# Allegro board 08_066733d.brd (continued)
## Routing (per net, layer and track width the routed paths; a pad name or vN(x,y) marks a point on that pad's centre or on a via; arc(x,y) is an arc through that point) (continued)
UNNAMED_6_CAP_I1_N1: length 6.6
  TOP w0.14: R20.2 14.5,48.92 12.8,48.92 C166.1 Y1.1
UNNAMED_6_CAP_I3_N1: length 5.5
  TOP w0.14: R22.2 16,52.13 C168.1 ; R27.1 17.65,53.34 17.2,52.89 C168.1 ; C168.1 Y1.3
UNNAMED_6_CAP_I19_N1: length 10.3
  TOP w0.14: U3.7 v1(48.92,20.85) ; R32.2 47.24,27.37 48,27.37 R29.2 48.32,27.19 v1(48.32,26.07) U3.24
  BOTTOM w0.381: v1(48.92,20.85) 48.92,22.4 48.25,23.06 C170.1 48.32,24.14 v1(48.32,26.07)
UNNAMED_6_CAP_I28_N1: length 7.5
  TOP w0.14: v1(51.31,27.18) 50.92,26.79 U3.20
  TOP w0.254: v1(52.96,24.51) 52.77,24.32 U3.16
  TOP w0.305: v1(52.96,24.51) 53.16,24.32 C171.1
  TOP w0.508: R33.2 C171.1
  BOTTOM w0.381: v1(52.96,24.51) 52.64,24.51 51.31,25.84 v1(51.31,27.18)
UNNAMED_6_CAP_I32_N1: length 7.7
  TOP w0.254: U3.11 50.92,21.46 v1(51.11,21.27) ; U3.15 52.77,23.82 v1(52.96,23.62) 53.41,23.18 R39.2
  TOP w0.381: v1(51.11,21.27) 51.11,21.24 51.18,21.17 51.18,21.01 C172.1
  TOP w0.508: R38.2 C172.1
  BOTTOM w0.381: v1(51.11,21.27) 51.11,22.15 52.58,23.62 v1(52.96,23.62)
UNNAMED_6_CAP_I37_N1: length 7.3
  TOP w0.14: R21.2 16.32,43.89 16.18,43.75 12.33,43.75 12.19,43.89 C167.1 Y2.1
UNNAMED_6_CAP_I39_N1: length 4.9
  TOP w0.14: C169.1 R28.1 R23.2 15.81,46.34 15.81,46.34 Y2.3
UNNAMED_6_ICSI5356X_I34_CLK0: length 1.6
  TOP w0.14: U3.22 49.92,26.86 R34.1
UNNAMED_6_ICSI5356X_I34_CLK1: length 1.4
  TOP w0.14: U3.21 R40.1
UNNAMED_6_ICSI5356X_I34_CLK2: length 2.8
  TOP w0.14: U3.18 52.51,25.32 52.71,25.51 52.71,27.19 R35.1
UNNAMED_6_ICSI5356X_I34_CLK4: length 2.3
  TOP w0.14: R36.1 53.09,22.1 52.95,22.24 52.95,23 52.63,23.32 U3.14
UNNAMED_6_ICSI5356X_I34_CLK6: length 1.4
  TOP w0.14: U3.10 R37.1
UNNAMED_6_ICSI5356X_I34_SSCDIS: length 2.7
  TOP w0.14: R31.1 R30.2 46.79,22.79 47.32,23.32 U3.5
UNNAMED_6_ICSI5356X_I34_XA: length 2.5
  TOP w0.14: Y3.3 46.8,26.29 47.77,25.32 U3.1
UNNAMED_6_ICSI5356X_I34_XB: length 6
  TOP w0.14: U3.2 47.72,24.82 47,24.1 47,23.69 46.75,23.43 44,23.43 43.86,23.57 Y3.1
UNNAMED_6_RES_I4_N2: length 2.6
  TOP w0.14: R18.2 18.72,50.74 R20.1 R22.1
UNNAMED_6_RES_I38_N1: length 2.9
  TOP w0.14: R19.2 18.72,46.34 R23.1 R21.1
UNNAMED_6_RES_I72_N1: length 1.6
  BOTTOM w0.14: R141.1 12.06,34.47 Y4.3
UNNAMED_6_RES_I73_N1: length 1.5
  BOTTOM w0.14: Y5.3 R142.1
UNNAMED_6_RES_I74_N1: length 1.7
  BOTTOM w0.14: R144.1 12.11,25.93 Y6.3
UNNAMED_6_RES_I75_N2: length 1.5
  BOTTOM w0.14: Y6.1 15.31,23.63 15.31,23.63 R143.2
UNNAMED_6_RES_I76_N2: length 1.6
  BOTTOM w0.14: Y5.1 R140.2
UNNAMED_6_RES_I77_N2: length 1.7
  BOTTOM w0.14: Y4.1 15.42,33.16 R139.2
UNNAMED_7_CN100PV2_I6_N44: length 9.8
  TOP w0.14: v1(1.27,16.51) 1.73,16.05 1.73,13.51 4.45,10.79 R41.2
  BOTTOM w0.14: v1(1.27,16.51) 1.4,16.64 J3.87
UNNAMED_7_CN100PV2_I6_N45: length 8.5
  TOP w0.14: R42.2 3.17,11.49 1.27,13.4 v1(1.27,15.75)
  BOTTOM w0.14: v1(1.27,15.75) 1.52,16 J3.89
UNNAMED_7_CN100PV2_I6_N46: length 13.5
  TOP w0.14: R43.2 v2(6.98,10.79)
  BOTTOM w0.14: J3.91 1.65,15.37 1.14,14.86 1.14,10.67 1.65,10.16 6.35,10.16 v2(6.98,10.79)
UNNAMED_7_CN100PV2_I6_N47: length 6.2
  TOP w0.14: R44.2 v2(1.91,10.92)
  BOTTOM w0.14: v2(1.91,10.92) 1.52,11.43 1.52,14.22 2.03,14.73 J3.93
UNNAMED_7_CN100PV2_I6_N48: length 8.2
  TOP w0.14: v2(5.59,10.79) 5.59,10.15 R45.2
  BOTTOM w0.14: J3.95 2.16,14.1 1.91,13.84 1.91,12.06 3.17,10.79 v2(5.59,10.79)
UNNAMED_8_ICIS25LP512_I14_SCK: length 3
  TOP w0.14: R50.1 R49.2 9.15,28.46 9.55,28.85 U4.16
UNNAMED_8_ICIS25LP512_I14_SO: length 3.1
  TOP w0.14: U4.8 v2(17.78,38.23)
  BOTTOM w0.14: R51.2 17.03,38.23 v2(17.78,38.23) R52.1
UNNAMED_9_ADSPSC59X_I10_HADC0VREFN: length 3.3
  TOP w0.305: U1.N20 41.53,51.34
  TOP w0.381: 41.53,51.34 41.93,51.74 R58.1
UNNAMED_9_ADSPSC59X_I10_HADC0VREFP: length 24.2
  TOP w0.203: U1.R19 v1(40.22,49.34)
  TOP w0.508: FL2.3 50.94,57.23 50.43,57.74 v1(49.52,57.74) C178.1 C177.1
  L8_SIG w0.292: v1(40.22,49.34) 41.06,49.46
  L8_SIG w0.381: 41.06,49.46 46.74,49.46
  L8_SIG w0.508: 46.74,49.46 47.5,50.22 47.5,51.84 48.3,52.64 49.32,52.64 50.32,53.64 50.32,56.94 v1(49.52,57.74)
UNNAMED_9_DIOLED_I5_N: length 2.9
  TOP w0.14: DS6.C 22.43,68.97 22.29,68.83 21.46,68.83 21.32,68.69 R59.1
UNNAMED_10_7408V3_I4_Y: length 15.5
  TOP w0.14: U13.1 58.32,30.79 58.87,30.24 59.42,30.24 59.56,30.1 60.96,30.1 v1(61.72,30.86) ; v1(61.72,38.23) 60.96,37.78 59.57,37.78 U11.4
  L4_SIG w0.127: v1(61.72,30.86) 60.71,31.88 60.71,37.21 v1(61.72,38.23)
UNNAMED_10_7408V3_I7_B: length 14.1
  TOP w0.14: S2.2B 60.18,36 56.66,36 S2.2A 56.09,35.43 55.25,35.43 54.8,34.99 54.8,33.46 54.23,32.89 54.23,30.73 55.11,29.85 R70.2 57.26,29.85 U13.2
UNNAMED_10_7408V3_I7_Y: length 8.8
  TOP w0.14: U13.4 60.31,28.9 60.71,28.5 60.71,24.26 60.25,23.8 U14.3 59.31,23.69 R71.2
UNNAMED_10_DIOLED_I24_N: length 2.1
  TOP w0.14: R73.1 DS5.C
UNNAMED_10_DIOLED_I40_N: length 2.1
  TOP w0.14: R77.1 DS4.C
UNNAMED_10_DIOLED_I62_N: length 2.1
  TOP w0.14: R76.1 DS1.C
UNNAMED_10_DIOLED_I63_N: length 2.1
  TOP w0.14: R74.1 DS2.C
UNNAMED_10_DIOLED_I64_N: length 2.1
  TOP w0.14: R72.1 DS3.C
UNNAMED_10_ICMC23018_I57_ADDR: length 2.7
  TOP w0.14: U24.11 14.11,65.46 R65.1 R64.2
UNNAMED_10_ICMC23018_I57_GPA0: length 9.1
  TOP w0.14: U24.15 12.07,62.86 v2(11.75,63.18)
  TOP w0.305: v2(5.46,64.81) R76.2
  L5_SIG w0.127: v2(11.75,63.18) 7.09,63.18 v2(5.46,64.81)
UNNAMED_10_ICMC23018_I57_GPA1: length 11.7
  TOP w0.14: U24.16 11.49,62.36 11.24,62.61 10.41,62.61 v2(9.78,61.98)
  TOP w0.305: R74.2 v2(3.56,64.81)
  L5_SIG w0.127: v2(3.56,64.81) 6.39,61.98 v2(9.78,61.98)
UNNAMED_10_ICMC23018_I57_GPA2: length 13.8
  TOP w0.14: v2(10.79,61.98) 10.91,61.86 U24.17
  TOP w0.305: v2(1.65,64.81) R72.2
  L5_SIG w0.127: v2(1.65,64.81) 5.06,61.4 10.22,61.4 v2(10.79,61.98)
UNNAMED_12_CAP_I12_N1: length 8.9
  TOP w0.254: v2(12.19,87.12) 12.2,87.11 U15.19
  BOTTOM w0.305: C185.1 v2(12.19,87.12) C186.1
  BOTTOM w0.508: E1.2 17.4,89.7 16.22,88.52 13.97,88.52 12.96,87.51 C186.1
UNNAMED_12_CAP_I23_N1: length 22.3
  TOP w0.254: U15.16 13.91,89.03 v2(13.08,89.03) ; v2(19.81,84.33) 19.43,84.61 U15.1
  TOP w0.762: v2(19.81,84.33) 20.57,84.33 20.83,84.58 20.83,90.3 20.45,90.68 13.46,90.68 13.08,90.3 v2(13.08,89.03)
  BOTTOM w0.305: R88.1 13.08,89.03 v2(13.08,89.03) ; v2(19.81,84.33) C187.1 C188.1
UNNAMED_12_CMOSPI3C3125_I39_B0: length 21.7
  TOP w0.14: U15.8 19.78,88.11 v2(19.81,88.14) ; v2(11.05,77.47) 11.43,77.74 U7.3
  L4_SIG w0.127: v2(19.81,88.14) 18.67,86.99 14.16,86.99 12.63,85.46 11.88,85.46 11.61,85.19 11.61,78.03 v2(11.05,77.47)
  BOTTOM w0.14: R86.2 11.44,77.86 v2(11.05,77.47)
UNNAMED_12_CMOSPI3C3125_I39_B1: length 16
  TOP w0.14: v2(17.4,82.68) 17.63,83.18 U15.32 ; U7.6 11.43,75.79 v2(11.05,76.07)
  L4_SIG w0.127: v2(17.4,82.68) 16.64,83.44 14.48,83.44 13.02,81.98 13.02,78.04 v2(11.05,76.07)
  BOTTOM w0.14: v2(11.05,76.07) 11.3,76.32 R87.2
UNNAMED_12_CMOSPI3C3125_I39_B2: length 14.9
  TOP w0.14: U7.8 19.3,75.14 v2(20.19,74.8) ; U15.2 19.43,85.11 v2(19.81,85.47)
  L8_SIG w0.127: v2(19.81,85.47) 19.18,84.84 19.18,75.82 v2(20.19,74.8)
UNNAMED_12_CMOSPI3C3125_I39_B3: length 9.1
  TOP w0.14: v2(16.38,82.68) 16.63,83.18 U15.30 ; U7.11 16.89,77.09 v2(16.89,77.09)
  L4_SIG w0.127: v2(16.89,77.09) 17.65,77.85 17.65,81.41 v2(16.38,82.68)
UNNAMED_12_CN10PODDEVEN_I8_N5: length 4.4
  TOP w0.14: P6.10 8.01,49.91 R85.1
UNNAMED_12_DIOLED_I30_N: length 1.9
  TOP w0.14: R89.1 DS7.C
UNNAMED_12_DIOLED_I31_N: length 1.9
  TOP w0.14: R90.1 DS8.C
UNNAMED_12_ICFT232RQ_I37_CBUS0: length 13.4
  TOP w0.14: v2(11.18,86.11) 11.81,85.47 12.66,85.47 12.8,85.61 U15.22 ; R89.2 v2(4.45,93.34)
  L4_SIG w0.127: v2(11.18,86.11) 4.45,92.84 v2(4.45,93.34)
UNNAMED_12_ICFT232RQ_I37_CBUS1: length 11.7
  TOP w0.14: U15.21 12.2,86.11 v2(12.19,86.11) ; R90.2 v2(6.35,93.34)
  L4_SIG w0.127: v2(12.19,86.11) 6.35,91.95 v2(6.35,93.34)
UNNAMED_12_ICFT232RQ_I37_RESET: length 3.5
  TOP w0.14: U15.18 12.54,87.61 12.44,87.71 12.11,87.71 11.68,88.14 v2(11.18,88.14)
  BOTTOM w0.14: R88.2 10.87,88.45 v2(11.18,88.14)
UNNAMED_13_ADLT8636_I1_BST: length 1.9
  TOP w0.254: C207.1 18.78,19 VR1.7
UNNAMED_13_ADLT8636_I1_EN: length 2.6
  TOP w0.203: v1(15.94,14.99) 16.14,14.99 VR1.14
  BOTTOM w0.305: R95.2 R96.2 15.62,15.29 15.93,14.99 v1(15.94,14.99)
UNNAMED_13_ADLT8636_I1_FB1: length 5.2
  TOP w0.254: 18.28,12.7 18.28,11.35 C210.2 ; 18.28,12.7 VR1.19 ; 18.28,12.7 18.54,12.7 18.53,12.7 18.78,12.95 VR1.20
  TOP w0.305: R106.1 R105.2 C210.2
UNNAMED_13_ADLT8636_I1_RT: length 2.5
  TOP w0.254: R98.1 16.13,11.94 17.28,13.09 VR1.17
UNNAMED_13_ADLT8636_I1_SYNC: length 2.6
  TOP w0.254: VR1.15 16.2,14.49 15.55,13.84
  TOP w0.305: 15.55,13.84 R94.1 R93.1
UNNAMED_13_ADLT8636_I1_TR: length 2.3
  TOP w0.254: C204.1 17.21,12.07 17.78,12.64 VR1.18
UNNAMED_13_ADLTC3307_I3_FB: length 3.6
  TOP w0.254: C220.2 R109.1 ; C220.2 U17.12 ; C220.2 R108.2
UNNAMED_13_ADLTC3307_I3_MODE: length 1.8
  TOP w0.14: U17.9 43.63,14.67 v1(43.56,14.61)
  BOTTOM w0.508: R5.2 42.97,14.61 v1(43.56,14.61)
UNNAMED_13_ADLTC3310_I4_FB: length 10.5
  TOP w0.254: U16.18 C208.2
  TOP w0.305: 33.66,13.58 C208.2 ; 33.66,13.58 34.54,13.58 R101.2 35.81,13.71 R102.1 ; 33.66,13.58 33.66,11.66 34.14,11.17 R97.2 R107.1 C209.1
UNNAMED_13_ADLTC3310_I4_ITH: length 9.5
  TOP w0.254: 31.68,13.58 32.38,14.28 U16.17
  TOP w0.305: C193.1 C195.1 31.68,13.58 31.94,13.32 31.94,10.73 32.5,10.17 R97.1
UNNAMED_13_ADLTC3310_I4_PGOOD: length 2.2
  TOP w0.254: U16.14 30.73,15.64 30.1,15.64 29.46,14.99 R99.1
UNNAMED_13_ADLTC3310_I4_SSTT: length 3.9
  TOP w0.254: U16.16 31.88,14.73 31.44,14.29 29.72,14.29 29.08,13.65 C202.1
UNNAMED_13_CAP_I72_N2: length 2.8
  TOP w0.305: C195.2 31.11,10.86 30.87,10.61 R91.1
UNNAMED_13_RES_I58_N2: length 1.7
  TOP w0.305: R102.2 36.07,12.71 37.27,12.71 R103.1
UNNAMED_14_CAP_I4_N1: length 2.7
  L2_PWR w0.14: v1(44.26,32.07) 45.21,33.02 v3(45.21,33.38)
  BOTTOM w0.14: v1(44.26,32.07) 44.32,32 C232.1
UNNAMED_14_CMOSSN74CB3T3125_I44_2B: length 4.1
  TOP w0.14: v1(22.16,35.18) 22.81,35.83 U12.6
  BOTTOM w0.14: v1(22.16,35.18) 22.81,35.83 R119.2 23.13,35.83 23.51,35.44 23.51,35.41 24.09,34.83 R68.1
UNNAMED_14_ICIS2XES04G_I1_CLK: length 1.9
  TOP w0.14: U19.M6 49.35,35.74 v1(49.21,35.74)
  BOTTOM w0.14: v1(49.21,35.74) 49.83,35.74 49.97,35.88 R110.2
UNNAMED_16_CAP_I2_N1: length 22.8
  TOP w0.305: P1.B9 31.73,92.22 P1.A4 ; P1.B4 29.23,92.22 P1.A9 29.23,89.77 C158.1
  TOP w0.508: C158.1 D15.C
  BOTTOM w0.508: v2(36.83,98.55) v2(36.83,97.79) 36.83,92.07 36,91.25 31.68,91.25 ; 31.68,91.25 29.46,91.25 29.28,91.43 P1.B4 ; 31.68,91.25 P1.B9
  vias: v2(42.16,99.63) v2(42.16,98.87) v2(42.16,98.11) v2(42.16,97.35)
UNNAMED_16_CAP_I15_N1: length 7.5
  TOP w0.508: R124.1 36.83,92.84 C159.1 36.83,92.97
  TOP w0.889: D16.C 39.37,95.16 39.15,95.38 R123.2 36.83,92.97
UNNAMED_16_CAP_I20_N1: length 2.7
  TOP w0.254: U6.21 v2(46.6,96.25)
  BOTTOM w0.508: v2(46.6,96.25) 48.18,96.25 C199.1
UNNAMED_16_CAP_I21_N1: length 1.9
  TOP w0.254: U6.23 v2(45.6,96.25)
  BOTTOM w0.508: C200.1 45.55,96.3 v2(45.6,96.25)
UNNAMED_16_CAP_I27_N2: length 1.3
  TOP w0.305: C160.2 R130.2
UNNAMED_16_CAP_I38_N1: length 47.6
  TOP w0.203: 30.48,99.45 P1.SH6 30.48,97.95 ; 30.48,94.86 P1.SH5 30.48,96.35
  TOP w0.508: P1.SH4 35.6,96.99 ; P1.SH4 33.9,99.31 ; P1.SH4 35.6,99.31 ; P1.SH4 33.9,96.99 ; 25.36,94.58 P1.SH2 ; P1.SH2 25.36,92.26 ; P1.SH2 27.06,94.58 ; P1.SH1 35.6,92.26 ; P1.SH1 35.6,94.58 ; P1.SH1 33.9,94.58 ; 25.36,96.99 P1.SH3 ; P1.SH3 25.36,99.31 ; P1.SH3 27.06,99.31 ; P1.SH3 27.06,96.99
  BOTTOM w0.508: P1.SH1 35.6,94.58 ; P1.SH1 33.9,94.58 ; P1.SH1 35.6,92.26 ; P1.SH4 35.6,99.31 ; P1.SH4 33.9,96.99 ; P1.SH4 35.6,96.99 ; P1.SH4 33.9,99.31 ; 25.36,92.26 P1.SH2 ; P1.SH2 25.36,94.58 ; P1.SH2 27.06,94.58 ; R80.1 C184.1 24.31,98.69 24.85,98.15 P1.SH3 ; P1.SH3 27.06,99.31 ; P1.SH3 27.06,96.99 ; P1.SH3 25.36,96.99 ; P1.SH3 25.36,99.31
UNNAMED_16_CN24PAB2GND6SHLD_I6_N5: length 25.9
  TOP w0.254: U6.2 43.94,94.22 v2(43.56,94.49) 43.94,94.72 U6.1
  TOP w0.305: P1.A5 31.23,90.31 31.25,90.29 31.25,90.29 31.44,90.1 31.44,90.1 31.62,89.92 31.62,88.24 31.32,87.93 D17.3 v2(30.59,87.21) ; v2(43.56,94.49) 43.56,94.49 R6.1
  L8_SIG w0.305: v2(30.59,87.21) 31.2,87.82 32.26,87.82 35.75,91.31 40.64,91.31 41.02,90.93 42.74,90.93 44.32,92.52 44.32,93.73 v2(43.56,94.49)
UNNAMED_16_CN24PAB2GND6SHLD_I7_N5: length 29.6
  TOP w0.254: U6.5 43.94,92.72 v2(43.56,92.96) 43.94,93.22 U6.4
  TOP w0.305: v2(43.56,92.96) 43.56,92.96 R66.1 ; D17.1 v2(29.59,89.23)
  L8_SIG w0.305: v2(29.59,89.23) 30.21,89.23 31.05,88.39 31.88,88.39 35.43,91.95 41.1,91.95 41.47,91.58 42.18,91.58 v2(43.56,92.96)
  BOTTOM w0.305: P1.B5 29.68,93.48 29.38,93.79 27.76,93.79 27.39,93.42 27.39,92.99 26.92,92.52 26.92,90.23 27.93,89.23 v2(29.59,89.23)
UNNAMED_16_ICSTUSB4500_I31_ADDR0: length 1.3
  TOP w0.254: U6.12 R125.1
UNNAMED_16_ICSTUSB4500_I31_ADDR1: length 2.8
  TOP w0.254: R126.1 49.09,90.54 49.09,92.01 48.87,92.22 U6.13
UNNAMED_16_ICSTUSB4500_I31_DISCH: length 12.2
  TOP w0.254: U6.9 46.11,90.93 v2(46.61,90.42)
  TOP w0.305: R146.2 v2(53.98,93.98)
  L8_SIG w0.305: v2(53.98,93.98) 53.98,92.58 53.09,91.69 46.91,91.69 46.61,91.39 v2(46.61,90.42)
UNNAMED_16_ICSTUSB4500_I31_VBUSENSNK: length 11.1
  TOP w0.254: v2(49.47,93.72) U6.16
  TOP w0.305: R129.2 v2(55.25,97.54)
  L8_SIG w0.305: v2(55.25,97.54) 51.69,97.54 51.05,96.9 51.05,94.03 50.75,93.72 v2(49.47,93.72)
UNNAMED_16_ICSTUSB4500_I31_VBUSVSDISCH: length 15.4
  TOP w0.254: v2(49.53,94.74) 49.51,94.72 U6.18
  TOP w0.305: R124.2 40.89,92.84 v2(40.89,92.84)
  L8_SIG w0.305: v2(40.89,92.84) 40.89,96.27 41.28,96.65 44.51,96.65 45.02,97.16 47.12,97.16 v2(49.53,94.74)
UNNAMED_16_RES_I22_N2: length 16
  TOP w0.305: R130.1 56.52,99.03 56.11,99.43 R129.1 53.62,99.43 Q5.4 53.4,99.4 53.4,100.27 53.09,100.58 47.88,100.58 47.62,100.33 R128.2 47.62,99.54 47.49,99.4 Q4.4
USB_DM: length 42.1
  TOP w0.133: v1(15.11,94.74) 14.86,94.49 14.86,94.22 14.97,94.11 D2.1 ; U15.15 14.63,89.28 14.73,89.39 14.73,89.53 v1(14.48,89.79) ; P1.A7 30.24,91.02 30.33,90.93 30.33,90.11 v1(30.06,89.84)
  L4_SIG w0.089: v1(15.11,94.74) 15.11,94.31 14.88,94.07 14.88,93.72 15.05,93.56 15.95,93.56 15.95,93.56 16.11,93.56 18.46,95.9 29.87,95.9 30.58,95.19 30.58,92.8 30.88,92.5 P1.B7 30.88,91.85 30.61,91.58 30.61,91.26 30.74,91.12 31.91,91.12 32.19,90.84 32.19,89.34 31.8,88.94 30.6,88.94 30.36,89.18 30.36,89.54 v1(30.06,89.84)
  BOTTOM w0.133: v1(15.11,94.74) 14.86,95 14.86,95.73 14.58,96.01 13.72,96.01 13.14,95.44 13.14,91.78 13.71,91.22 14.4,91.22 14.73,90.89 14.73,90.04 v1(14.48,89.79)
USB_DP: length 40.4
  TOP w0.133: P1.A6 30.63,90.92 30.63,90.13 v1(30.92,89.84) ; v1(14.35,94.74) 14.61,94.49 14.61,94.24 14.47,94.11 D2.2 ; v1(15.24,89.79) 14.99,89.53 14.99,89.42 15.12,89.28 U15.14
  L4_SIG w0.089: v1(14.35,94.74) 14.35,94.31 14.57,94.09 14.57,93.59 14.92,93.25 16.18,93.25 18.57,95.64 29.76,95.64 30.32,95.08 30.32,92.79 30.08,92.55 P1.B6 30.08,91.84 30.3,91.62 30.3,91.13 30.57,90.86 31.8,90.86 31.93,90.73 31.93,89.45 31.68,89.21 30.77,89.21 30.67,89.31 30.67,89.6 v1(30.92,89.84)
  BOTTOM w0.133: v1(14.35,94.74) 14.61,95 14.61,95.62 14.47,95.76 13.82,95.76 13.4,95.34 13.4,91.89 13.81,91.47 14.51,91.47 14.99,91 14.99,90.04 v1(15.24,89.79)
USB_TYPEC: length 9.6
  TOP w0.254: v2(43.37,95.5) 45.07,95.5 U6.24
  TOP w0.305: v2(52.07,96.01) D18.C ; v2(55.25,96.52) C160.1 ; v2(53.98,96.52) R146.1
  TOP w0.508: v2(17.78,93.66) D1.1
  BOTTOM w0.305: v2(42.04,96.01) C201.1
  BOTTOM w0.508: v1(22.29,89.73) E1.1 C183.1
  vias: v2(4.57,17.14) v2(4.57,16.38) v2(4.57,15.62) v2(5.46,17.14) v2(5.46,16.38) v2(5.46,15.62) v2(48.77,99.57) v2(48.77,98.81) v2(48.77,98.04) v2(48.77,97.28) v2(49.53,99.57) v2(49.53,98.81) v2(49.53,98.04) v2(49.53,97.28)
VTT: length 25
  TOP w0.254: U2.6 56.37,73.39
  TOP w0.267: U2.9 54.87,73.92 54.99,74.04
  BOTTOM w0.203: RN7.8 34.06,85.69 34.06,86.22 ; 33.56,86.54 RN7.7
  BOTTOM w0.254: 36.27,86.34 36.27,85.69 RN4.5 ; 44.02,76.69 43.28,76.69 RN1.7 ; 44.02,76.69 44.02,77.19 ; 44.02,76.69 44.02,76.19 43.42,76.19 RN1.8 ; 44.02,72.99 43.37,72.99 RN2.8 ; RN6.5 34.57,67.39 34.57,66.74 ; 44.02,80.39 RN3.6 ; 44.02,79.39 43.37,79.39 RN3.8 ; 44.02,77.19 44.02,77.69 43.42,77.69 RN1.5 ; 44.02,77.19 43.28,77.19 RN1.6 ; RN5.5 37.77,67.39 37.77,66.74 ; RN4.6 36.77,86.34 ; 44.02,73.49 RN2.7 ; RN4.7 37.27,86.34 ; 37.27,66.74 RN5.6 ; RN5.7 36.77,66.74 ; RN3.5 43.37,80.89 44.02,80.89 ; 33.07,66.74 33.07,67.39 RN6.8 ; 34.07,66.74 RN6.6 ; 33.57,66.74 RN6.7 ; 37.77,86.34 37.77,85.69 RN4.8 ; RN5.8 36.27,67.39 36.27,66.74 ; 44.02,74.49 43.37,74.49 RN2.5 ; 44.02,73.99 RN2.6 ; 44.02,79.89 RN3.7
  vias: v2(56.77,77.72) v2(56.77,76.96) v2(56.77,76.2) v2(56.77,75.44) v2(56.77,74.68) v2(56.77,73.91) v2(57.53,77.72) v2(57.53,76.96) v2(57.53,76.2) v2(57.53,75.44) v2(57.53,74.68) v2(57.53,73.91) v2(57.73,72.95) v2(57.73,72.18) v2(58.29,77.72) v2(58.29,76.96) v2(58.29,76.2) v2(58.29,75.44) v2(58.29,74.68) v2(58.29,73.91) v2(59.05,77.72) v2(59.05,76.96) v2(59.05,76.2) v2(59.05,75.44) v2(59.05,74.68) v2(59.05,73.91)

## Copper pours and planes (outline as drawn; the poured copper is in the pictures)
DGND on TOP (solid shape): 62.04,71.88 59.84,71.88 59.84,78.1 62.04,78.1
DGND on TOP (solid shape): 62.04,66.93 59.84,66.93 59.84,71.5 62.04,71.5
DGND on TOP: 10.34,23.34 13.03,23.34 13.03,25.39 12.83,25.59 10.48,25.59 10.34,25.45
DGND on TOP: 45.77,15.53 46.74,15.53 46.91,15.7 48.51,15.7 48.73,15.93 50.66,15.93 51.05,16.32 51.05,20.07 48.26,20.07 48.26,17.08 47.62,16.45 46.41,16.45 45.77,15.81
DGND on TOP: 30.43,12.87 27.6,12.87 27.3,12.57 27.3,8.83 27.62,8.51 38.35,8.51 38.8,8.95 38.8,14.41 36.94,16.28 33.32,16.28 33.32,16 34.17,16 35.62,14.54 36.45,14.54 36.83,14.16 36.83,13.83 38.23,13.83 38.35,13.7 38.35,9.59 37.85,9.08 29.72,9.08 29.15,9.65 29.15,11.05 29.39,11.3 30.47,11.3 30.47,12.83
DGND on TOP: 18.16,15.63 16.25,15.63 15.51,16.37 15.51,16.55 10.16,16.55 10.15,16.54 10.15,13.67 10.41,13.4 13.21,13.4 13.4,13.59 13.4,14.61 13.74,14.95 15.51,14.95 15.91,15.35 18.16,15.35
DGND on TOP: 62.8,100.9 62.8,0.7 0.7,0.7 0.7,100.9 ; 53 cut-outs
DGND on TOP: 45.77,14.31 45.77,13.22 45.85,13.14 46.93,13.14 47.12,12.95 47.12,12.07 46.93,11.88 46.05,11.88 46.05,11.04 46.36,10.73 47.94,10.73 49.19,11.98 49.19,13.48 49.02,13.65 46.42,13.65 46.21,13.86 46.21,14.31
DGND on TOP: 44.4,15.53 43.43,15.53 43.26,15.7 41.66,15.7 41.44,15.93 39.51,15.93 39.12,16.32 39.12,20.07 41.78,20.07 41.78,17.21 42.55,16.45 43.76,16.45 44.4,15.81
DGND on TOP: 14.66,13.15 13.6,13.15 13.46,13.02 13.46,9.21 14.03,8.64 23.94,8.64 24.24,8.94 24.24,11.09 22.24,11.09 21.76,10.61 20.02,10.61 20.02,9.41 19.81,9.21 17.84,9.21 17.54,9.51 17.54,10.59 17.51,10.61 15.76,10.61 14.66,11.72
DGND on BOTTOM: 37.63,23.19 37.63,16.28 39.24,14.67 46.61,14.67 47.18,15.24 47.18,17.11 47.17,17.12 42.13,17.12 41.91,17.34 41.91,22.63 41.35,23.19
DGND on BOTTOM: 0.7,100.9 62.8,100.9 62.8,0.7 0.7,0.7 ; 52 cut-outs
DGND on L2_PWR: 50.8,100.9 62.8,100.9 62.8,65.15 57.15,65.15 57.15,74.04 57.08,74.22 56.9,74.3 50.8,74.3
DGND on L2_PWR: 40.13,39.18 44.83,39.18 44.83,34.8 44.91,34.62 45.09,34.54 49.15,34.54 49.15,33.78 49.22,33.6 49.4,33.53 50.48,33.53 50.48,30.92 40.13,30.92 ; 1 cut-out
DGND on L3_GND: 0.7,100.9 62.8,100.9 62.8,0.7 0.7,0.7
DGND on L3_GND: 28.28,9.89 28.29,9.88 28.31,9.87 35.61,9.87 35.63,9.87 35.94,9.99 36.26,9.87 36.27,9.87 38.05,9.87 38.07,9.88 38.07,9.89 38.07,16.46 38.07,16.48 38.05,16.48 37.67,16.48 37.66,16.48 37.65,16.47 37.21,16.17 36.77,16.47 36.76,16.48 36.75,16.48 36.28,16.48 36.26,16.48 36.25,16.47 35.81,16.17 35.38,16.47 35.37,16.48 35.35,16.48 35.26,16.48 35.25,16.48 35.24,16.47 34.8,16.17 34.36,16.46 34.34,16.47 34.32,16.45 34.32,14.92 34.34,14.9 34.36,14.91 35.27,14.73 34.36,14.55 34.34,14.57 34.32,14.54 34.32,13.65 34.31,13.63 34.29,13.63 28.31,13.63 28.29,13.62 28.28,13.6
DGND on L6_PWR: 30.42,88.01 62.8,88.01 62.8,72.33 51.82,72.33 51.64,72.25 51.56,72.07 51.56,65.28 35.12,65.28 35.12,66.99 38.29,66.99 38.47,67.07 38.54,67.25 38.54,68.26 40.45,68.26 40.63,68.34 40.7,68.52 40.7,70.74 41.53,70.74 41.71,70.81 41.78,70.99 41.78,72.39 42.61,72.39 42.79,72.46 42.86,72.64 42.86,74.68 42.79,74.86 42.61,74.93 41.85,74.93 41.85,75.63 42.61,75.63 42.79,75.7 42.86,75.88 42.86,77.91 42.79,78.09 42.61,78.17 41.85,78.17 41.85,78.8 42.61,78.8 42.79,78.88 42.86,79.06 42.86,81.92 42.79,82.09 42.61,82.17 39.94,82.17 39.94,86.04 39.87,86.22 39.69,86.3 30.42,86.3
DGND on L9_GND: 62.8,100.9 62.8,0.7 0.7,0.7 0.7,100.9
VDD_CONNECTOR on TOP (solid shape): 3.71,14.45 4.45,13.72 5.71,13.72 5.71,12.57 3.3,12.57 2.44,13.44 2.44,18.41 3.71,18.41
VDD_DMC on TOP: 59.44,71.5 57.24,71.5 57.24,70.39 56.85,69.99 55.37,69.99 55.37,66.67 59.44,66.67
VDD_DMC on TOP: 40.07,23.81 40.07,21.08 40.7,20.45 42.16,20.45 43.37,19.24 46.94,19.24 46.94,21.07 46.8,21.21 44.39,21.21 43.82,21.78 43.82,22.1 41.91,24 40.26,24
VDD_DMC on BOTTOM: 47.17,17.93 42.37,17.93 42.37,20.57 42.24,20.7 40.7,20.7 40.01,21.4 40.01,23.11 40.83,23.94 42.48,23.94 44.2,22.22 45.72,22.22 45.91,22.03 45.91,21.27 47.17,20.02
VDD_DMC on L6_PWR: outline of 101 points within 0.7,0.7 62.8,88.01
VDD_EXT on TOP (solid shape): 10.67,5.71 7.75,5.71 7.75,7.62 10.67,7.62
VDD_EXT on TOP (solid shape): 59.18,61.21 57.15,61.21 56.36,60.42 56.36,59.44 52.06,59.44 52.06,62.66 53.47,64.07 59.18,64.07
VDD_EXT on L5_SIG (solid shape): 10.67,5.71 7.75,5.71 7.75,7.62 10.67,7.62
VDD_EXT on TOP: 21.68,20.12 21.68,26.96 20.95,27.69 15.24,27.69 14.4,26.85 14.4,23.99 18.8,23.99 20.1,22.68 20.1,20.12
VDD_EXT on TOP: 33.32,16.5 34.24,16.5 34.42,16.32 37.66,16.32 37.83,16.5 37.83,18.58 35.83,18.58 35.83,18.24 35.61,18.02 34.59,18.02 34.59,17.43 34.44,17.28 33.32,17.28
VDD_EXT on TOP: 54.42,72.37 54.42,73.66 54.17,73.91 52.34,73.91 52.01,73.58 52.01,72.12 53.39,72.12 53.64,72.37
VDD_EXT on TOP: 39.84,15.32 39.18,14.66 39.18,9.72 39.75,9.14 50.42,9.14 51.24,9.97 51.24,14.29 50.22,15.32 45.78,15.32 45.77,15.31 45.77,15.03 46.56,15.03 46.89,14.7 47.57,14.7 48.26,14.02 49.16,14.02 49.61,13.57 49.61,11.83 48.01,10.22 43.88,10.22 43.55,10.55 43.55,11.88 42.41,11.88 42.23,12.07 42.23,13.72 42.54,14.03 44.4,14.03 44.4,15.31 44.39,15.32
VDD_EXT on TOP: 30.94,17.28 29.98,17.28 29.82,17.43 29.82,18.02 28.82,18.02 28.64,18.2 28.64,18.83 26.63,18.83 26.61,18.81 26.61,15.81 26.67,15.75 29.4,15.75 29.65,16 30.94,16
VDD_EXT on BOTTOM: 21.74,23.55 17.79,23.55 17.27,24.07 17.27,27.18 17.4,27.3 21.21,27.3 21.74,26.77
VDD_EXT on L2_PWR: outline of 88 points within 0.7,0.7 62.8,100.9 ; 2 cut-outs
VDD_EXT on L5_SIG: outline of 98 points within 3.07,5.74 26.33,44.11
VDD_INPUT on TOP: 4.98,21.34 4.98,17.91 6.35,17.91 7.43,18.99 9.84,18.99 10.15,18.68 10.15,17.75 14.82,17.75 16.23,16.35 16.87,16.35 16.87,16.63 16.45,16.63 16.32,16.76 16.32,18.54 15.52,19.34 13.5,19.34 13.03,19.82 13.03,22.12 10.25,22.12 9.46,21.34
VDD_INPUT on TOP: 25.92,17.75 21.25,17.75 19.84,16.35 19.2,16.35 19.2,16.63 19.61,16.63 19.81,16.83 19.81,18.61 20.55,19.34 22.56,19.34 23.03,19.81 25.78,19.81 25.92,19.67
VDD_INPUT on BOTTOM: 9.91,21.21 13.08,21.21 14.22,20.07 25.65,20.07 25.65,17.53 9.91,17.53
VDD_INT on TOP: 28.04,28.78 28.04,22.29 36.22,22.29 36.22,28.78
VDD_INT on BOTTOM: 28.47,25.96 28.47,20.51 28.49,20.5 36.39,20.5 36.39,26.67 35.81,27.24 31.06,27.24 29.78,25.96
VDD_INT on L2_PWR: 24.89,65.66 41.97,65.66 41.97,62.17 42.05,61.99 42.23,61.91 48.51,61.91 48.51,55.52 29.46,55.52 29.43,55.52 29.3,55.47 29.25,55.34 29.25,50.55 29.3,50.42 29.43,50.37 32.45,50.37 32.57,50.42 32.63,50.55 32.63,53.54 34.87,53.54 34.87,50.1 34.93,49.98 35.05,49.92 36.64,49.92 36.77,49.98 36.82,50.1 36.82,53.54 37.29,53.54 37.29,52.07 37.34,51.94 37.47,51.89 38.94,51.89 38.94,45.77 12.13,45.77 12.13,48.51 12.05,48.69 11.87,48.77 8.89,48.77 8.71,48.69 8.64,48.51 8.64,24.45 8.71,24.27 8.89,24.19 29.08,24.19 29.26,24.27 29.34,24.45 29.34,27.3 38.29,27.3 38.29,18.03 26.16,18.03 25.98,17.96 25.91,17.78 25.91,14.86 25.98,14.68 26.16,14.61 27.75,14.61 27.75,13.46 27.82,13.28 28,13.21 37.78,13.21 37.78,9.08 2.67,9.08 2.49,9.01 2.41,8.83 2.41,7.11 0.7,7.11 0.7,61.98 24.64,61.98 24.82,62.05 24.89,62.23
VDD_REF on TOP (solid shape): 62.23,52.83 60.71,52.83 60.71,54.61 59.69,55.63 59.69,58.55 59.05,59.18 57.66,59.18 57.66,60.45 59.05,60.45 59.69,61.09 59.69,63.18 62.23,63.18
VDD_REF on L6_PWR: 47.1,60.13 62.8,60.13 62.8,49.4 56.13,49.4 55.95,49.33 55.88,49.15 55.88,33.72 53.09,33.72 52.91,33.64 52.83,33.46 52.83,27.94 52.91,27.76 53.09,27.69 56.32,27.69 56.32,21.53 48.77,21.53 48.77,26.61 48.69,26.79 48.51,26.86 44.7,26.86 44.7,42.55 44.63,42.72 44.45,42.8 33.45,42.8 33.45,47.24 33.44,47.31 33.4,47.37 31.93,48.84 31.93,52.21 41.92,52.21 42,52.15 42.1,52.13 42.28,52.21 42.35,52.39 42.35,55.39
(no net) on L7_SIG: 62.8,100.9 62.8,0.7 0.7,0.7 0.7,100.9 ; 70 cut-outs
DMC0_VREF on TOP (solid shape): 49.78,81.03 49.78,65.02 44.2,65.02 44.2,79.63 43.94,80.01 42.04,80.01 41.91,80.14 41.91,81.53 42.04,81.66 49.15,81.66
DMC0_VREF on BOTTOM (solid shape): 47.29,56.21 44.32,56.21 44.32,57.02 47.29,57.02
DMC0_VREF on L8_SIG (solid shape): 45.34,65.02 44.96,64.64 44.96,57.15 45.21,56.9 45.72,56.9 45.72,56.13 44.58,56.13 44.2,56.51 44.2,65.79 44.45,66.04 45.34,66.04
UNNAMED_2_CAP_I43_N1 on TOP (solid shape): 39.62,84.07 39.62,82.04 40.01,81.66 41.28,81.66 41.47,81.47 41.47,67.88 40.89,67.31 34.16,67.31 33.53,67.94 33.53,70.24 33.26,70.52 31.75,70.52 31.75,72.26 34.42,72.26 35.05,71.63 35.05,69.34 35.43,68.96 39.5,68.96 39.88,69.34 39.88,80.14 39.5,80.52 38.86,80.52 38.48,80.9 38.48,83.55 38.23,83.81 37.54,83.81 37.27,83.51 37.27,80.71 36.96,80.39 35.81,80.39 35.81,82.04 36.83,82.04 36.83,84.2 37.08,84.45 39.24,84.45
UNNAMED_13_ADLT8636_I1_SW1 on TOP: 14.4,20.19 16.13,20.19 16.76,19.56 16.76,17.91 17.14,17.53 17.14,16.84 18.41,16.84 18.41,17.91 17.91,18.41 17.91,19.81 18.29,20.19 18.8,20.19 18.8,21.84 14.4,21.84
UNNAMED_13_ADLTC3307_I3_SW1 on TOP: 44.7,15.61 44.7,16.65 44.13,17.21 43.37,17.21 43.23,17.35 43.23,18.48 46.94,18.48 46.94,17.35 46.8,17.21 46.04,17.21 45.47,16.64 45.47,16.63 45.47,15.61
UNNAMED_13_ADLTC3310_I4_SW1 on TOP: 31.24,17.79 31.24,18.99 30.3,19.93 30.28,19.93 30.28,20.89 33.99,20.89 33.99,19.93 33.02,18.96 33.02,17.79
UNNAMED_16_CAP_I2_N1 on TOP (solid shape): 44.96,96.65 42.29,96.65 41.53,97.41 38.86,97.41 37.72,96.27 36.46,96.27 36.46,100.01 36.53,100.08 44.96,100.08
UNNAMED_16_CAP_I2_N1 on BOTTOM: 44.8,99.62 43.57,99.62 43.12,100.08 41.78,100.08 41.59,99.89 41.59,97.16 41.97,96.77 42.74,96.77 42.99,97.03 42.99,97.47 43.38,97.87 44.8,97.87
UNNAMED_16_CAP_I38_N1 on TOP, BOTTOM: 24.89,99.31 24.89,92.27 25.27,91.88 26.42,91.88 27.37,92.84 27.37,94.55 27.5,94.68 33.4,94.68 33.53,94.55 33.53,92.65 34.29,91.88 35.81,91.88 36.07,92.14 36.07,99.25 35.69,99.63 25.21,99.63
USB_TYPEC on TOP (solid shape): 8.79,14.86 4.09,14.86 4.09,17.53 6.63,17.53 7.52,18.41 8.79,18.41
USB_TYPEC on TOP (solid shape): 52.56,98.57 52.77,98.36 53.21,98.36 53.21,98.95 53.97,98.95 53.97,97.25 53.21,97.25 53.21,97.85 52.77,97.85 52.58,97.66 52.58,96.65 48.26,96.65 48.26,96.98 48.01,97.23 45.47,97.23 45.47,98.96 48.01,98.96 48.26,99.21 48.26,100.2 52.56,100.2
USB_TYPEC on BOTTOM: 46.76,99.62 46.76,97.87 48.18,97.87 48.26,97.79 48.26,97.03 48.51,96.77 49.97,96.77 50.04,96.84 50.04,99.89 49.91,100.01 48.45,100.01 48.06,99.62
USB_TYPEC on L6_PWR: 62.8,100.9 62.8,88.52 18.73,88.52 18.55,88.44 18.48,88.27 18.48,70.74 7.11,70.74 6.93,70.66 6.86,70.48 6.86,14.61 0.7,14.61 0.7,100.9 ; 1 cut-out
VTT on TOP: 59.44,80.01 52.71,80.01 52.71,78.49 54.86,78.49 54.86,74.3 54.74,74.17 54.74,72.37 55.01,72.37 55.01,73.05 55.05,73.09 57.15,73.09 57.24,73 57.24,71.69 59.44,71.69
VTT on BOTTOM: 32.66,67.34 38.42,67.34 38.42,68.52 38.48,68.58 40.13,68.58 40.39,68.83 40.39,70.74 40.64,70.99 43.43,70.99 43.69,71.25 45.07,71.25 45.07,72.64 43.63,72.64 43.63,74.8 45.07,74.8 45.07,75.82 43.69,75.82 43.69,77.98 45.07,77.98 45.07,78.99 43.63,78.99 43.63,81.15 45.07,81.15 45.07,82.99 42.99,82.99 42.29,83.69 42.29,84.77 41.76,85.31 39.92,85.31 39.33,85.89 38.58,85.89 38.52,85.95 33.44,85.95 33.44,88.26 51.44,88.26 51.82,87.88 51.82,80.14 52.11,79.84 59.56,79.84 59.56,71.88 56.9,71.88 56.9,72.58 55.44,74.04 52.07,74.04 51.69,73.66 51.69,66.55 51.44,66.29 43.75,66.29 43.3,65.84 40.75,65.84 40.58,66.1 32.66,66.1

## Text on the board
Ref Des/Silkscreen Bottom: EV-SC598-SOM
User.Comments: 5.    SEE CRYSTAL OSCILLATOR PIN 1 DETAILS: | 7.    SMOOTHEN EDGES AND FREE FROM BURRS AFTER DEPANELIZATION PROCESS. | 4.    SEE DETAIL A FOR D15 AND D18. | 6.    SINGULATE BOARD AFTER ASSEMBLY PROCESS | A. SEE DETAIL B FOR CRYSTALS - Y1-Y6. | DETAIL A | DETAIL B
Ref Des/Assembly Top: A | C
Ref Des/Silkscreen Top: A | C | EV-SC598-SOM
XSECTION_CHART: L1 | L2 | L3 | L4 | L5 | L6 | L7 | L8 | L9 | L10 | DESIGN CROSS SECTION CHART | ___________________________ | TOTAL THICKNESS 62 MIL | 1-10 | 1-2
PAGE_OUTLINE: B | C | D | CHANGES PER ECR-104316 | CHANGES PER ECR-105397 | CHANGES PER ECR-107846 | 26AUG21 | 02NOV21 | 29MAR22 | D. HARRINGTON | CUSTOMER EVALUATION Z
DIMENSION: - | SEE DETAIL A | " " | V-SCORE | DETAIL A | (REF) | PRIMARY SIDE | SECONDARY SIDE | DIA MAX | SEE NOTE 15
User.11: A | C | (CHECK DATASHEET) | BOTTOM VIEW
User.15: 17.    PANELED SOLDER PASTE STENCIL SHOULD BE SENT TO THE CUSTOMER | 15.    THRU VIAS FILLED WITH NON-CONDUCTIVE EPOXY AND PLATED OVER. | 16.    LASER VIAS TO BE COPPER FILLED (PLATED SHUT) AND PLANARIZED | NOTE: ALL IMPEDANCE TOLERANCE +/-10% | LAYER | L1 | L4 | L5 | L7 | L8 | L10 | SE = SINGLE ENDED, DP = DIFFERENTIAL PAIR | 50 OHMS SE | 90 OHMS DP | 100 OHMS DP | IMPEDANCE | REFERENCE | L2 | L3 | L6 | L9 | LINE WIDTH | 5.25 MILS | 5.5 MILS | 3.5 MILS | 5 MILS | 3 MILS | 4.75 MILS | 7.5 MILS | SPACE | N/A | 7 MILS | IMPEDANCE TABLE
User.24: 08-      -07 | L2 PWR
User.25: 08-      -08 | L3 GND
User.26: 08-      -09 | L4 SIG
User.27: 08-      -10 | L5 SIG
User.28: 08-      -11 | L6 PWR
User.29: 08-      -12 | L7 SIG
User.30: 08-      -13 | L8 SIG
User.31: 08-      -14 | L9 GND
User.32: 3 | BLIND VIAS L1-L2 | DIA MAX | SEE NOTE 16
User.45: FIGURE | SIZE | 4.0 | 8.0 | 12.0 | 16.0 | 29.0 | 63.0 | 35.0 | 125.0 | 48.0x24.0 | PLATED | NON-PLATED | DRILL CHART:TOP to BOTTOM | DRILL CHART:TOP to L2_PWR | ALL UNITS ARE IN MILS | QTY | 1206 | 8 | 539 | 14 | 10 | 4 | 6 | TOLERANCE/NOTES
